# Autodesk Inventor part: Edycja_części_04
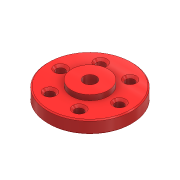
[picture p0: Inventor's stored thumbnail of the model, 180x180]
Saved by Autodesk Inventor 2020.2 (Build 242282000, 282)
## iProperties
Created: 2016-07
Part Number: Edycja_części_04
Material: Ogólne
Document SubType Name: Modeling
Designer: F.Stasiak
Density: 1 g/cm^3
Appearance: Jasnoczerwona
Manager: www.cadconsulting.pl
Company: Fabian Stasiak CAD Consulting
Author: F.Stasiak
Subject: Zbiór ćwiczeń. Autodesk Inventor 2020. Kurs podstawowy
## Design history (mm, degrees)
sketch "Szkic1"
  geometry: C1 r 40 at (0, 0); 1 further point
  constraints: 1 centre point, 1 coincident
  dimensions: "d0" = 80 diameter of C1
extrude "Wyciągnięcie proste1" new body sketch "Szkic1" distance "d1" = 12; taper "d2" = 0 deg
hole "Otwór1" diameter "d5" = 12; stored, may be unused: countersink angle "d9" = 90 deg, drill point angle "d11" = 118 deg; dims "d3" = 10, "d4" = 10, "d6" = 6, "d7" = 4, "d8" = 2, "d10" = 8
sketch "Szkic2"
  geometry: C1 r 6 at (0, 0) reference; 2 further points
  constraints: 1 horizontal alignment
  dimensions: "d34" = 28 distance of C1.centre point (-28, 0)
hole "Otwór2" sketch "Szkic2" at (-28, 0) diameter "d13" = 8; stored, may be unused: countersink angle "d17" = 90 deg, drill point angle "d19" = 118 deg; dims "d14" = 6, "d15" = 12, "d16" = 2, "d18" = 8
pattern_circular "Szyk kołowy1" dims angle "d21" = 360 deg
chamfer "Faza1" distance "d23" = 1; stored, may be unused: second distance "d24" = 2, angle "d25" = 45 deg
sketch "Szkic4"
  geometry: C1 r 6 at (0, 0) reference; C2 r 39 at (0, 0) reference; C3 r 17.5 at (0, 0)
  constraints: 1 centre point, 1 coincident
  dimensions: "d31" = 35 diameter of C3
extrude "Wyciągnięcie proste3" join sketch "Szkic4" distance "d32" = 5; taper "d33" = 0 deg
node "Bryła1"
